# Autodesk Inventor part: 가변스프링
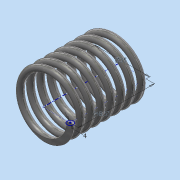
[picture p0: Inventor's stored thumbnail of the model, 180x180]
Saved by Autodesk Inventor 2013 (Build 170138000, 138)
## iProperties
Created: 2014-12
Part Number: 가변스프링
Material: 강철, 탄소
Document SubType Name: Modeling
Designer: user
Density: 1 g/cm^3
Mass: 10.1907 g
Surface Area: 103.211 cm^2
Volume: 10.1907 cm^3
Author: user
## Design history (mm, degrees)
sketch "스케치1"
  geometry: L1 (0, 0)-(17.5, 0); L2 (17.5, 0)-(17.5, 48.5); L3 (17.5, 48.5)-(0, 48.5); L4 (0, 48.5)-(0, 0); C1 r 2 at (17.5, 0)
  constraints: 8 end point, 2 parallel, 1 centre point, 1 coincident, 1 horizontal, 1 perpendicular
  dimensions: "d0" = 35 diameter of L2 L4; "d2" = 48.5 distance of L1.end L2.end (derived); "d4" = 4 diameter of C1
feature "코일1" sketch "스케치1" pitch "d5" = 10; turns "d7" = 7.5; dims "d6" = 48.5 (= d2), "d8" = 0, angle "d9" = 90 deg, angle "d10" = 90 deg, "d11" = 0, "d12" = 0
sketch "스케치2"
  geometry: L1 (-19.5, 0)-(-15.5, 0) reference; 1 further point
  constraints: 1 horizontal alignment
  node "절단 모서리 투영1"
node "작업 평면1"
sketch "스케치3"
  geometry: L1 (15.5, 0)-(19.5, 0) reference; 1 further point
  constraints: 1 horizontal alignment
extrude "돌출1" cut sketch "스케치3" distance "d13" = 10; taper "d14" = 0 deg
extrude "돌출2" cut sketch "스케치2" distance "d15" = 10; taper "d16" = 0 deg
node "솔리드1"
node "절단 모서리 투영2"
